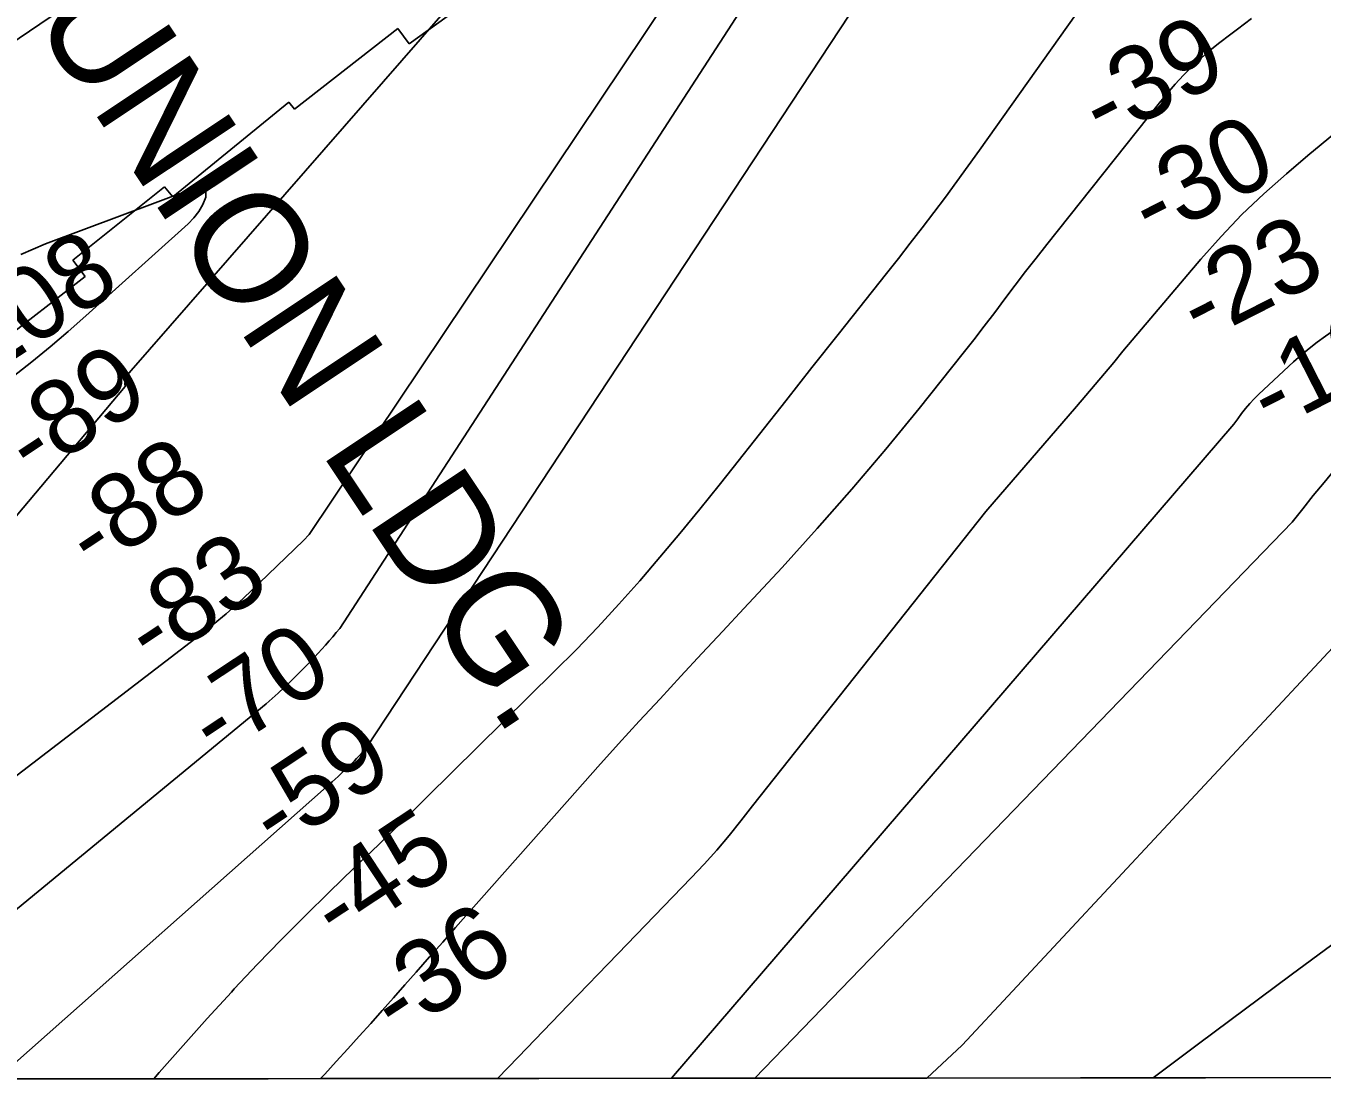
# Model space of a CAD drawing. Extents: x 3297753 to 3335611, y 652252 to 677623.
# Drawn here: x 3314328 to 3315492, y 657631 to 658590 of the extents above; entities that cross this region are included whole.
import ezdxf

# ---------------------------------------------------------------- set-up
doc = ezdxf.new("R2010")
doc.units = 0
for name, color, linetype in [('V-GRID-FRAM', 7, 'Continuous'), ('V-RIVR-EDGE', 7, 'Continuous'), ('V-RIVR-RANG', 7, 'Continuous'), ('V-RRAP-RVMT', 7, 'Continuous'), ('V-TOPO-DPTH', 7, 'Continuous'), ('V-TOPO-GNAM-IDEN', 7, 'Continuous'), ('V-TOPO-MAJR', 7, 'Continuous'), ('V-TOPO-MINR', 7, 'Continuous')]:
    doc.layers.add(name, color=color, linetype=linetype)

msp = doc.modelspace()

# ---------------------------------------------------------------- linework, layer by layer
at = {"layer": 'V-GRID-FRAM'}
msp.add_lwpolyline([(3301859.6, 675814.9), (3333399.1, 675847), (3333425.5, 657662.7), (3301870.2, 657630.6), (3301859.6, 675814.9)], dxfattribs=at)
at = {"layer": 'V-RIVR-EDGE'}
msp.add_spline([(3319472.9, 662096.8), (3319451.4, 662084.8), (3319431.4, 662073.3), (3319412.8, 662065.4), (3319386.6, 662059.7), (3319355.1, 662056.1), (3319321.5, 662047.4), (3319286.7, 662035.9), (3319261.8, 662024.4), (3319253.9, 662022.3), (3319244, 662022.3), (3319236.9, 662020.3), (3319220.3, 662007.1), (3319214.1, 661999.2), (3319197.9, 661992.6), (3319174.7, 661985.2), (3319135.2, 661974.5), (3319095.8, 661962.6), (3319061.8, 661950.7), (3319035.7, 661940.8), (3319017, 661932.5), (3319004.2, 661925.1), (3318977.6, 661914.4), (3318949.4, 661908.7), (3318929.1, 661903.3), (3318893.4, 661894.3), (3318836.2, 661878.7), (3318802.2, 661869.7), (3318784.3, 661864.3), (3318761.1, 661859.4), (3318735.4, 661848.3), (3318707.2, 661836.3), (3318683.9, 661831.8), (3318667.8, 661829.8), (3318647.9, 661824.9), (3318612.2, 661812.5), (3318583.6, 661801.4), (3318550.8, 661789.5), (3318517.2, 661780.8), (3318486.9, 661770.5), (3318459.1, 661757.8), (3318437.1, 661748.7), (3318401.1, 661732.6), (3318376.3, 661719.7), (3318350.3, 661712.4), (3318322.7, 661702.9), (3318295.6, 661690.6), (3318275.9, 661686.7), (3318257.8, 661681.1), (3318243.7, 661673.2), (3318214.4, 661661.5), (3318180.6, 661645.8), (3318148.4, 661630.1), (3318131.5, 661619.4), (3318111.1, 661604.8), (3318079.5, 661575), (3318056.4, 661560.4), (3318032.7, 661542.4), (3318016.3, 661532.3), (3317961.5, 661489.7), (3317862.7, 661415.5), (3317830, 661391.9), (3317829.4, 661388.6), (3317827.2, 661382.9), (3317810.8, 661375.6), (3317786, 661359.9), (3317761.1, 661342.5), (3317743.6, 661322.8), (3317726.1, 661300.9), (3317708.6, 661279), (3317696.7, 661270.6), (3317673.6, 661255.4), (3317601.3, 661201.5), (3317560.7, 661171.7), (3317529.1, 661153.2), (3317513.8, 661140.3), (3317483.9, 661117.2), (3317464.2, 661105.5), (3317423.5, 661083), (3317409.4, 661079.1), (3317401.5, 661079.1), (3317375, 661065.7), (3317364.3, 661058.9), (3317348.5, 661051.1), (3317330.5, 661046.6), (3317307.3, 661033.2), (3317289.3, 661024.8), (3317263.9, 661012.4), (3317240.8, 661008.5), (3317230.1, 661004), (3317228.4, 661000.1), (3317221.6, 660998.4), (3317196.2, 660991.2), (3317170.3, 660981.7), (3317149.4, 660978.3), (3317103.2, 660961), (3317073.3, 660949.8), (3317034.3, 660929.6), (3316996, 660910), (3316948, 660887), (3316914.7, 660873.5), (3316886, 660860.6), (3316880.9, 660856.2), (3316871.3, 660848.3), (3316865.7, 660846.6), (3316855.5, 660846.6), (3316850.4, 660846.6), (3316844.2, 660840.5), (3316839.7, 660839.9), (3316835.8, 660840.5), (3316830.7, 660836.6), (3316818.8, 660828.7), (3316813.8, 660828.1), (3316808.1, 660827), (3316803.6, 660827), (3316796.8, 660818.6), (3316785, 660809.6), (3316774.8, 660802.9), (3316771.4, 660796.1), (3316765.2, 660779.2), (3316755.6, 660759.5), (3316745.9, 660744.3), (3316732.4, 660728.6), (3316712.6, 660717.9), (3316683.9, 660703.4), (3316676.5, 660701.1), (3316664.7, 660695.5), (3316651.7, 660680.3), (3316633, 660666.9), (3316616.1, 660656.2), (3316590.1, 660637.1), (3316544.4, 660603.4), (3316510, 660581), (3316472.7, 660551.7), (3316428.7, 660523.1), (3316390.3, 660495.6), (3316363.8, 660477.6), (3316349.7, 660469.8), (3316341.2, 660464.7), (3316335, 660464.7), (3316325.4, 660464.8), (3316313.6, 660461.4), (3316289.9, 660457), (3316257.2, 660443.5), (3316237.5, 660436.3), (3316207, 660423.9), (3316177.1, 660405.4), (3316154.5, 660393.1), (3316131.9, 660375.1), (3316110.5, 660362.2), (3316095.3, 660353.2), (3316080, 660338), (3316051.2, 660312.7), (3316013.9, 660270.6), (3315988.5, 660245.8), (3315960.3, 660217.2), (3315939.9, 660200.9), (3315925.8, 660185.1), (3315911.1, 660173.9), (3315895.3, 660159.9), (3315882.9, 660145.8), (3315867.6, 660130.1), (3315849, 660120), (3315837.7, 660109.3), (3315808.9, 660080.1), (3315786.9, 660062.1), (3315758.1, 660038.5), (3315733.8, 660018.8), (3315725.3, 660002.5), (3315692, 659976.7), (3315659.8, 659949.1), (3315603.4, 659904.2), (3315571.2, 659873.3), (3315569.5, 659873.3), (3315558.8, 659868.8), (3315547.5, 659863.2), (3315527.7, 659844.1), (3315506.3, 659828.4), (3315477.5, 659812.1), (3315461.1, 659805.9), (3315440.8, 659793.6), (3315429.5, 659781.8), (3315402.4, 659758.2), (3315361.8, 659731.8), (3315304.2, 659696.4), (3315255.7, 659666.7), (3315169.9, 659624.7), (3315140, 659611.8), (3315123.7, 659603.4), (3315098.8, 659588.8), (3315044.6, 659551.1), (3314989.9, 659507.3), (3314954.3, 659474.7), (3314934, 659462.4), (3314926.1, 659452.8), (3314915.9, 659440.5), (3314897.8, 659423.6), (3314866.8, 659396.1), (3314844.7, 659376.4), (3314848.7, 659370.7), (3314825, 659355), (3314801.8, 659342.7), (3314762.3, 659320.8), (3314730.2, 659303.4), (3314711, 659290.5), (3314664.7, 659256.3), (3314628.6, 659235.5), (3314603.2, 659218.1), (3314584.5, 659209.7), (3314564.8, 659208), (3314555.8, 659204.7), (3314546.8, 659196.2), (3314528.1, 659174.9), (3314492.5, 659118.6), (3314473.8, 659095), (3314450.7, 659074.8), (3314428.7, 659060.2), (3314423, 659054.6), (3314416.2, 659044.4), (3314398.1, 659027.6), (3314375.6, 659007.9), (3314366.5, 659005.1), (3314353.6, 659002.3), (3314347.4, 658997.3), (3314346.8, 658988.8), (3314351.3, 658983.2), (3314350.7, 658974.2), (3314342.8, 658961.8), (3314329.2, 658955.1), (3314311.7, 658940.4), (3314310, 658930.3), (3314294.2, 658921.9), (3314283.5, 658914.6), (3314276.1, 658903.9), (3314272.7, 658896), (3314237.7, 658871.3), (3314206.7, 658853.4), (3314198.2, 658851.1), (3314192, 658850.6), (3314180.2, 658846.1), (3314172.3, 658836.5), (3314164.4, 658823.6), (3314142.3, 658810.1), (3314120.9, 658792.7), (3314097.2, 658778.7), (3314086.5, 658769.1), (3314082.5, 658762.9), (3314080.2, 658754.5), (3314072.3, 658750), (3314036.8, 658734.3), (3314006.3, 658722), (3313997.3, 658716.4), (3313939.7, 658673.7), (3313888.3, 658635), (3313863.5, 658615.3), (3313820.6, 658586.7), (3313772.6, 658558), (3313732, 658532.8), (3313718.5, 658524.4), (3313711.1, 658521.6), (3313702.7, 658521.6), (3313693.1, 658518.8), (3313674.5, 658511.5), (3313646.8, 658494.7), (3313626.5, 658479), (3313619.7, 658475), (3313610.1, 658464.3), (3313605, 658449.1), (3313597.1, 658444.7), (3313577.9, 658428.9), (3313554.8, 658407.6), (3313537.8, 658387.3), (3313525.4, 658364.2), (3313506.1, 658331.6), (3313489.7, 658309.7)], degree=3, dxfattribs=at)
at = {"layer": 'V-RRAP-RVMT'}
for p, q in [((3314773, 658646.6), (3314671.8, 658573.4)), ((3314661.6, 658587.4), (3314568.9, 658514.8)), ((3314671.8, 658573.4), (3314661.6, 658587.4)), ((3314563.7, 658521.1), (3314459.6, 658436)), ((3314568.9, 658514.8), (3314563.7, 658521.1)), ((3314452.2, 658444.9), (3314369.7, 658379)), ((3314459.6, 658436), (3314452.2, 658444.9)), ((3314369.7, 658379), (3314380.9, 658364.3)), ((3314380.9, 658364.3), (3314192.9, 658219.1))]:
    msp.add_line(p, q, dxfattribs=at)
at = {"layer": 'V-TOPO-DPTH'}
for points in [[(3315957.1, 658632.6), (3315890.1, 658586.3), (3315823.1, 658539.9), (3315756.2, 658493.4), (3315689.4, 658446.7), (3315495.1, 658310.8), (3315487.6, 658305.4), (3315480.4, 658299.8), (3315473.3, 658293.8), (3315466.5, 658287.7), (3315435.3, 658258.6), (3315431.1, 658254.5), (3315427.1, 658250.3), (3315423.3, 658245.8), (3315419.7, 658241.3), (3315416.3, 658236.6), (3315412.9, 658231.8), (3314907.7, 657643.9)], [(3314907.7, 657643.9), (3315412.9, 658231.8), (3315416.3, 658236.6), (3315419.7, 658241.3), (3315423.3, 658245.8), (3315427.1, 658250.3), (3315431.1, 658254.5), (3315435.3, 658258.6), (3315466.5, 658287.7), (3315473.3, 658293.8), (3315480.4, 658299.8), (3315487.6, 658305.4), (3315495.1, 658310.8), (3315689.4, 658446.7), (3315756.2, 658493.4), (3315823.1, 658539.9), (3315890.1, 658586.3), (3315957.1, 658632.6)], [(3313169.9, 657642.1), (3314592.3, 657643.6), (3314596, 657647.5), (3314606.4, 657658.9), (3314616.7, 657670.3), (3314627, 657681.7), (3314637.3, 657693.2), (3314647.5, 657704.7), (3314657.7, 657716.2), (3314668, 657727.8), (3314678.2, 657739.3), (3314690.3, 657753.1), (3314696.1, 657759.7), (3314702, 657766.3), (3314707.8, 657772.9), (3314713.6, 657779.4), (3314823, 657903.2), (3314841.4, 657923.8), (3314859.9, 657944.4), (3314878.5, 657964.8), (3314897.3, 657985), (3314916.1, 658005.3), (3314934.9, 658025.5), (3314953.8, 658045.7), (3314972.6, 658066), (3315006.9, 658102.9), (3315038.6, 658137.9), (3315069.7, 658173.2), (3315100.1, 658209.3), (3315130, 658245.8), (3315169.6, 658295.4), (3315179.2, 658307.5), (3315188.6, 658319.7), (3315198, 658331.9), (3315207.2, 658344.3), (3315216.4, 658356.6), (3315225.7, 658368.9), (3315235.2, 658381), (3315244.7, 658393.2), (3315346, 658520.4), (3315353, 658528.9), (3315360.2, 658537.2), (3315367.7, 658545.2), (3315375.4, 658553), (3315383.4, 658560.5), (3315391.6, 658567.8), (3315400.1, 658574.7), (3315408.8, 658581.4), (3315416.1, 658586.8), (3315428.6, 658596.1)], [(3315428.6, 658596.1), (3315416.1, 658586.8), (3315408.8, 658581.4), (3315400.1, 658574.7), (3315391.6, 658567.8), (3315383.4, 658560.5), (3315375.4, 658553), (3315367.7, 658545.2), (3315360.2, 658537.2), (3315353, 658528.9), (3315346, 658520.4), (3315244.7, 658393.2), (3315235.2, 658381), (3315225.7, 658368.9), (3315216.4, 658356.6), (3315207.2, 658344.3), (3315198, 658331.9), (3315188.6, 658319.7), (3315179.2, 658307.5), (3315169.6, 658295.4), (3315130, 658245.8), (3315100.1, 658209.3), (3315069.7, 658173.2), (3315038.6, 658137.9), (3315006.9, 658102.9), (3314972.6, 658066), (3314953.8, 658045.7), (3314934.9, 658025.5), (3314916.1, 658005.3), (3314897.3, 657985), (3314878.5, 657964.8), (3314859.9, 657944.4), (3314841.4, 657923.8), (3314823, 657903.2), (3314713.6, 657779.4), (3314707.8, 657772.9), (3314702, 657766.3), (3314696.1, 657759.7), (3314690.3, 657753.1), (3314678.2, 657739.3), (3314668, 657727.8), (3314657.7, 657716.2), (3314647.5, 657704.7), (3314637.3, 657693.2), (3314627, 657681.7), (3314616.7, 657670.3), (3314606.4, 657658.9), (3314596, 657647.5), (3314592.3, 657643.6)], [(3314592.3, 657643.6), (3314751.4, 657643.7), (3314770, 657663.1), (3314814.7, 657709.5), (3314859.4, 657755.8), (3314925.3, 657823.9), (3314936.9, 657836.4), (3314948.3, 657849), (3314959.3, 657862.1), (3314970, 657875.3), (3314980.4, 657888.8), (3315189.9, 658153.3), (3315271.4, 658247.6), (3315279.9, 658257.4), (3315288.3, 658267.3), (3315296.6, 658277.2), (3315304.9, 658287.2), (3315313.1, 658297.2), (3315321.4, 658307.2), (3315329.8, 658317.1), (3315338.2, 658327), (3315383.3, 658380.1), (3315401.4, 658400.3), (3315420.1, 658420), (3315439.7, 658438.7), (3315460, 658456.7), (3315479.4, 658473.2), (3315510.1, 658498.5)], [(3315510.1, 658498.5), (3315479.4, 658473.2), (3315460, 658456.7), (3315439.7, 658438.7), (3315420.1, 658420), (3315401.4, 658400.3), (3315383.3, 658380.1), (3315338.2, 658327), (3315329.8, 658317.1), (3315321.4, 658307.2), (3315313.1, 658297.2), (3315304.9, 658287.2), (3315296.6, 658277.2), (3315288.3, 658267.3), (3315279.9, 658257.4), (3315271.4, 658247.6), (3315189.9, 658153.3), (3314980.4, 657888.8), (3314970, 657875.3), (3314959.3, 657862.1), (3314948.3, 657849), (3314936.9, 657836.4), (3314925.3, 657823.9), (3314859.4, 657755.8), (3314814.7, 657709.5), (3314770, 657663.1), (3314751.4, 657643.7), (3314907.7, 657643.9)], [(3314907.7, 657643.9), (3315137, 657644.1), (3315168.7, 657673.6), (3315530.4, 658061.9)], [(3315530.4, 658061.9), (3315168.7, 657673.6), (3315137, 657644.1), (3315637.6, 657644.6)]]:
    msp.add_lwpolyline(points, dxfattribs=at)
at = {"layer": 'V-TOPO-MAJR'}
for points in [[(3315292.2, 658630.1), (3315184.3, 658477.8), (3315174.2, 658463.7), (3315164, 658449.7), (3315153.7, 658435.7), (3315143.2, 658421.9), (3315132.7, 658408.1), (3315122.1, 658394.4), (3315111.4, 658380.7), (3315100.7, 658367.1), (3315057.4, 658312.4), (3315033.8, 658282.5), (3315010.2, 658252.6), (3314986.5, 658222.7), (3314962.9, 658192.8), (3314950.4, 658177), (3314932.9, 658155.2), (3314915.2, 658133.5), (3314897.2, 658112.1), (3314879, 658090.8), (3314860.4, 658069.9), (3314841.5, 658049.3), (3314822.1, 658029.1), (3314802.3, 658009.3), (3314687.9, 657896.5), (3314666.1, 657875.1), (3314644.2, 657853.8), (3314622.3, 657832.6), (3314600.3, 657811.4), (3314578.5, 657790), (3314556.9, 657768.4), (3314535.7, 657746.4), (3314514.8, 657724.2), (3314512.3, 657721.4), (3314490.4, 657697.5), (3314468.8, 657673.4), (3314447.3, 657649), (3314442.4, 657643.4)], [(3314482.9, 658422.8), (3314486.4, 658429), (3314489.3, 658435.7), (3314489.1, 658439.9), (3314487.7, 658442.9), (3314484.6, 658444.3), (3314480.4, 658444.5), (3314345.2, 658393.8), (3314323, 658384.2)], [(3314316.1, 658274.4), (3314332.8, 658287.6), (3314349.3, 658301.1), (3314365.5, 658314.9), (3314381.5, 658329), (3314473.4, 658411.8), (3314478.4, 658417.1), (3314482.9, 658422.8)]]:
    msp.add_lwpolyline(points, dxfattribs=at)
at = {"layer": 'V-TOPO-MINR'}
for points in [[(3315169.2, 659137.4), (3315169.6, 659135.7), (3315169.2, 659133.4), (3315163.7, 659127.2), (3315157.8, 659121.4), (3315151.6, 659116), (3314422, 658279.8), (3314420.3, 658277.7), (3314418.6, 658275.5), (3314417.4, 658273.2), (3314416.6, 658270.7), (3314416.4, 658268.2), (3314416.6, 658265.6), (3314081.5, 657867.3), (3314006.7, 657811.8), (3313860.7, 657707), (3313831.2, 657686.3), (3313801.5, 657665.9), (3313771.4, 657646.1), (3313766, 657642.7)], [(3314217.3, 658508.2), (3315001.5, 659039.7), (3315014.4, 659048.3), (3315027.3, 659057), (3315040.3, 659065.5), (3315053.2, 659074), (3315075.2, 659088.3), (3315077.2, 659089.6), (3315081.5, 659092.1), (3315083.6, 659093.3), (3315165.3, 659138.1), (3315167.7, 659138.1), (3315169.2, 659137.4)], [(3315165.6, 659004.2), (3314582.1, 658132.6), (3314576.9, 658127.2), (3314529.4, 658081.4), (3314518.5, 658071.2), (3314507.4, 658061.3), (3314495.9, 658051.7), (3314484.2, 658042.4), (3314156.2, 657791.1)], [(3315163.1, 658901.8), (3314609.6, 658048.1), (3314606.4, 658044.4), (3314603.2, 658040.7), (3314600, 658037), (3314596.8, 658033.2), (3314593.5, 658029.5), (3314590.2, 658025.9), (3314586.8, 658022.3), (3314583.4, 658018.8), (3314564.9, 658000.2), (3314559.7, 657995.1), (3314554.3, 657990.1), (3314548.8, 657985.3), (3314543.3, 657980.5), (3314133.4, 657643.1)], [(3315102, 658652.3), (3314634.3, 657941.9), (3314632.5, 657939.7), (3314630.6, 657937.6), (3314628.7, 657935.4), (3314626.7, 657933.3), (3314624.7, 657931.2), (3314622.7, 657929.2), (3314620.6, 657927.2), (3314610.5, 657917.6), (3314608, 657915.1), (3314605.4, 657912.8), (3314602.8, 657910.4), (3314600.2, 657908.1), (3314301.3, 657643.3)], [(3314907.7, 657643.9), (3315412.9, 658231.8), (3315416.3, 658236.6), (3315419.7, 658241.3), (3315423.3, 658245.8), (3315427.1, 658250.3), (3315431.1, 658254.5), (3315435.3, 658258.6), (3315466.5, 658287.7), (3315473.3, 658293.8), (3315480.4, 658299.8), (3315487.6, 658305.4), (3315495.1, 658310.8), (3315689.4, 658446.7), (3315756.2, 658493.4), (3315823.1, 658539.9), (3315890.1, 658586.3), (3315957.1, 658632.6)], [(3314592.3, 657643.6), (3314596, 657647.5), (3314606.4, 657658.9), (3314616.7, 657670.3), (3314627, 657681.7), (3314637.3, 657693.2), (3314647.5, 657704.7), (3314657.7, 657716.2), (3314668, 657727.8), (3314678.2, 657739.3), (3314690.3, 657753.1), (3314696.1, 657759.7), (3314702, 657766.3), (3314707.8, 657772.9), (3314713.6, 657779.4), (3314823, 657903.2), (3314841.4, 657923.8), (3314859.9, 657944.4), (3314878.5, 657964.8), (3314897.3, 657985), (3314916.1, 658005.3), (3314934.9, 658025.5), (3314953.8, 658045.7), (3314972.6, 658066), (3315006.9, 658102.9), (3315038.6, 658137.9), (3315069.7, 658173.2), (3315100.1, 658209.3), (3315130, 658245.8), (3315169.6, 658295.4), (3315179.2, 658307.5), (3315188.6, 658319.7), (3315198, 658331.9), (3315207.2, 658344.3), (3315216.4, 658356.6), (3315225.7, 658368.9), (3315235.2, 658381), (3315244.7, 658393.2), (3315346, 658520.4), (3315353, 658528.9), (3315360.2, 658537.2), (3315367.7, 658545.2), (3315375.4, 658553), (3315383.4, 658560.5), (3315391.6, 658567.8), (3315400.1, 658574.7), (3315408.8, 658581.4), (3315416.1, 658586.8), (3315428.6, 658596.1)], [(3314982.5, 657644), (3315465.3, 658143.7), (3315474.7, 658155.7), (3315484.2, 658167.6), (3315493.9, 658179.3), (3315503.7, 658191), (3315509.3, 658197.5), (3315516.7, 658205.5), (3315524.5, 658213.1), (3315532.9, 658220), (3315541.7, 658226.6), (3315743.7, 658364.6), (3315808.6, 658408.6), (3315873.6, 658452.4), (3315939, 658495.8), (3316004.4, 658539), (3316092.3, 658596.6)], [(3314751.4, 657643.7), (3314770, 657663.1), (3314814.7, 657709.5), (3314859.4, 657755.8), (3314925.3, 657823.9), (3314936.9, 657836.4), (3314948.3, 657849), (3314959.3, 657862.1), (3314970, 657875.3), (3314980.4, 657888.8), (3315189.9, 658153.3), (3315271.4, 658247.6), (3315279.9, 658257.4), (3315288.3, 658267.3), (3315296.6, 658277.2), (3315304.9, 658287.2), (3315313.1, 658297.2), (3315321.4, 658307.2), (3315329.8, 658317.1), (3315338.2, 658327), (3315383.3, 658380.1), (3315401.4, 658400.3), (3315420.1, 658420), (3315439.7, 658438.7), (3315460, 658456.7), (3315479.4, 658473.2), (3315510.1, 658498.5)], [(3315137, 657644.1), (3315168.7, 657673.6), (3315530.4, 658061.9)], [(3315340.2, 657644.3), (3315381, 657675), (3315464.2, 657736.9), (3315628.7, 657858.1)]]:
    msp.add_lwpolyline(points, dxfattribs=at)

# ---------------------------------------------------------------- texts
at = {"layer": 'V-RIVR-RANG'}
for s, rotation, p in [('-39', 27.0052, (3315295.1, 658484.4)), ('-30', 27.0052, (3315339.3, 658394.7)), ('-23', 27.0052, (3315382.9, 658304.7)), ('-108', 33.5352, (3314265.5, 658255.5)), ('-16', 27.0052, (3315445.9, 658224.6)), ('-89', 33.5352, (3314333.9, 658180.9)), ('-88', 33.5352, (3314388.3, 658097)), ('-83', 33.5352, (3314441.2, 658012)), ('-70', 33.5352, (3314498.6, 657930.1)), ('-59', 33.5352, (3314553.2, 657846.4)), ('-45', 33.5352, (3314608.5, 657763)), ('-36', 33.5352, (3314661.8, 657678.4))]:
    msp.add_text(s, height=67, rotation=rotation, dxfattribs=at).set_placement(p)
at = {"layer": 'V-TOPO-GNAM-IDEN'}
msp.add_text('UNION LDG.', height=100, rotation=303.6834, dxfattribs=at).set_placement((3314331.8, 658597))

doc.saveas('drawing.dxf')
